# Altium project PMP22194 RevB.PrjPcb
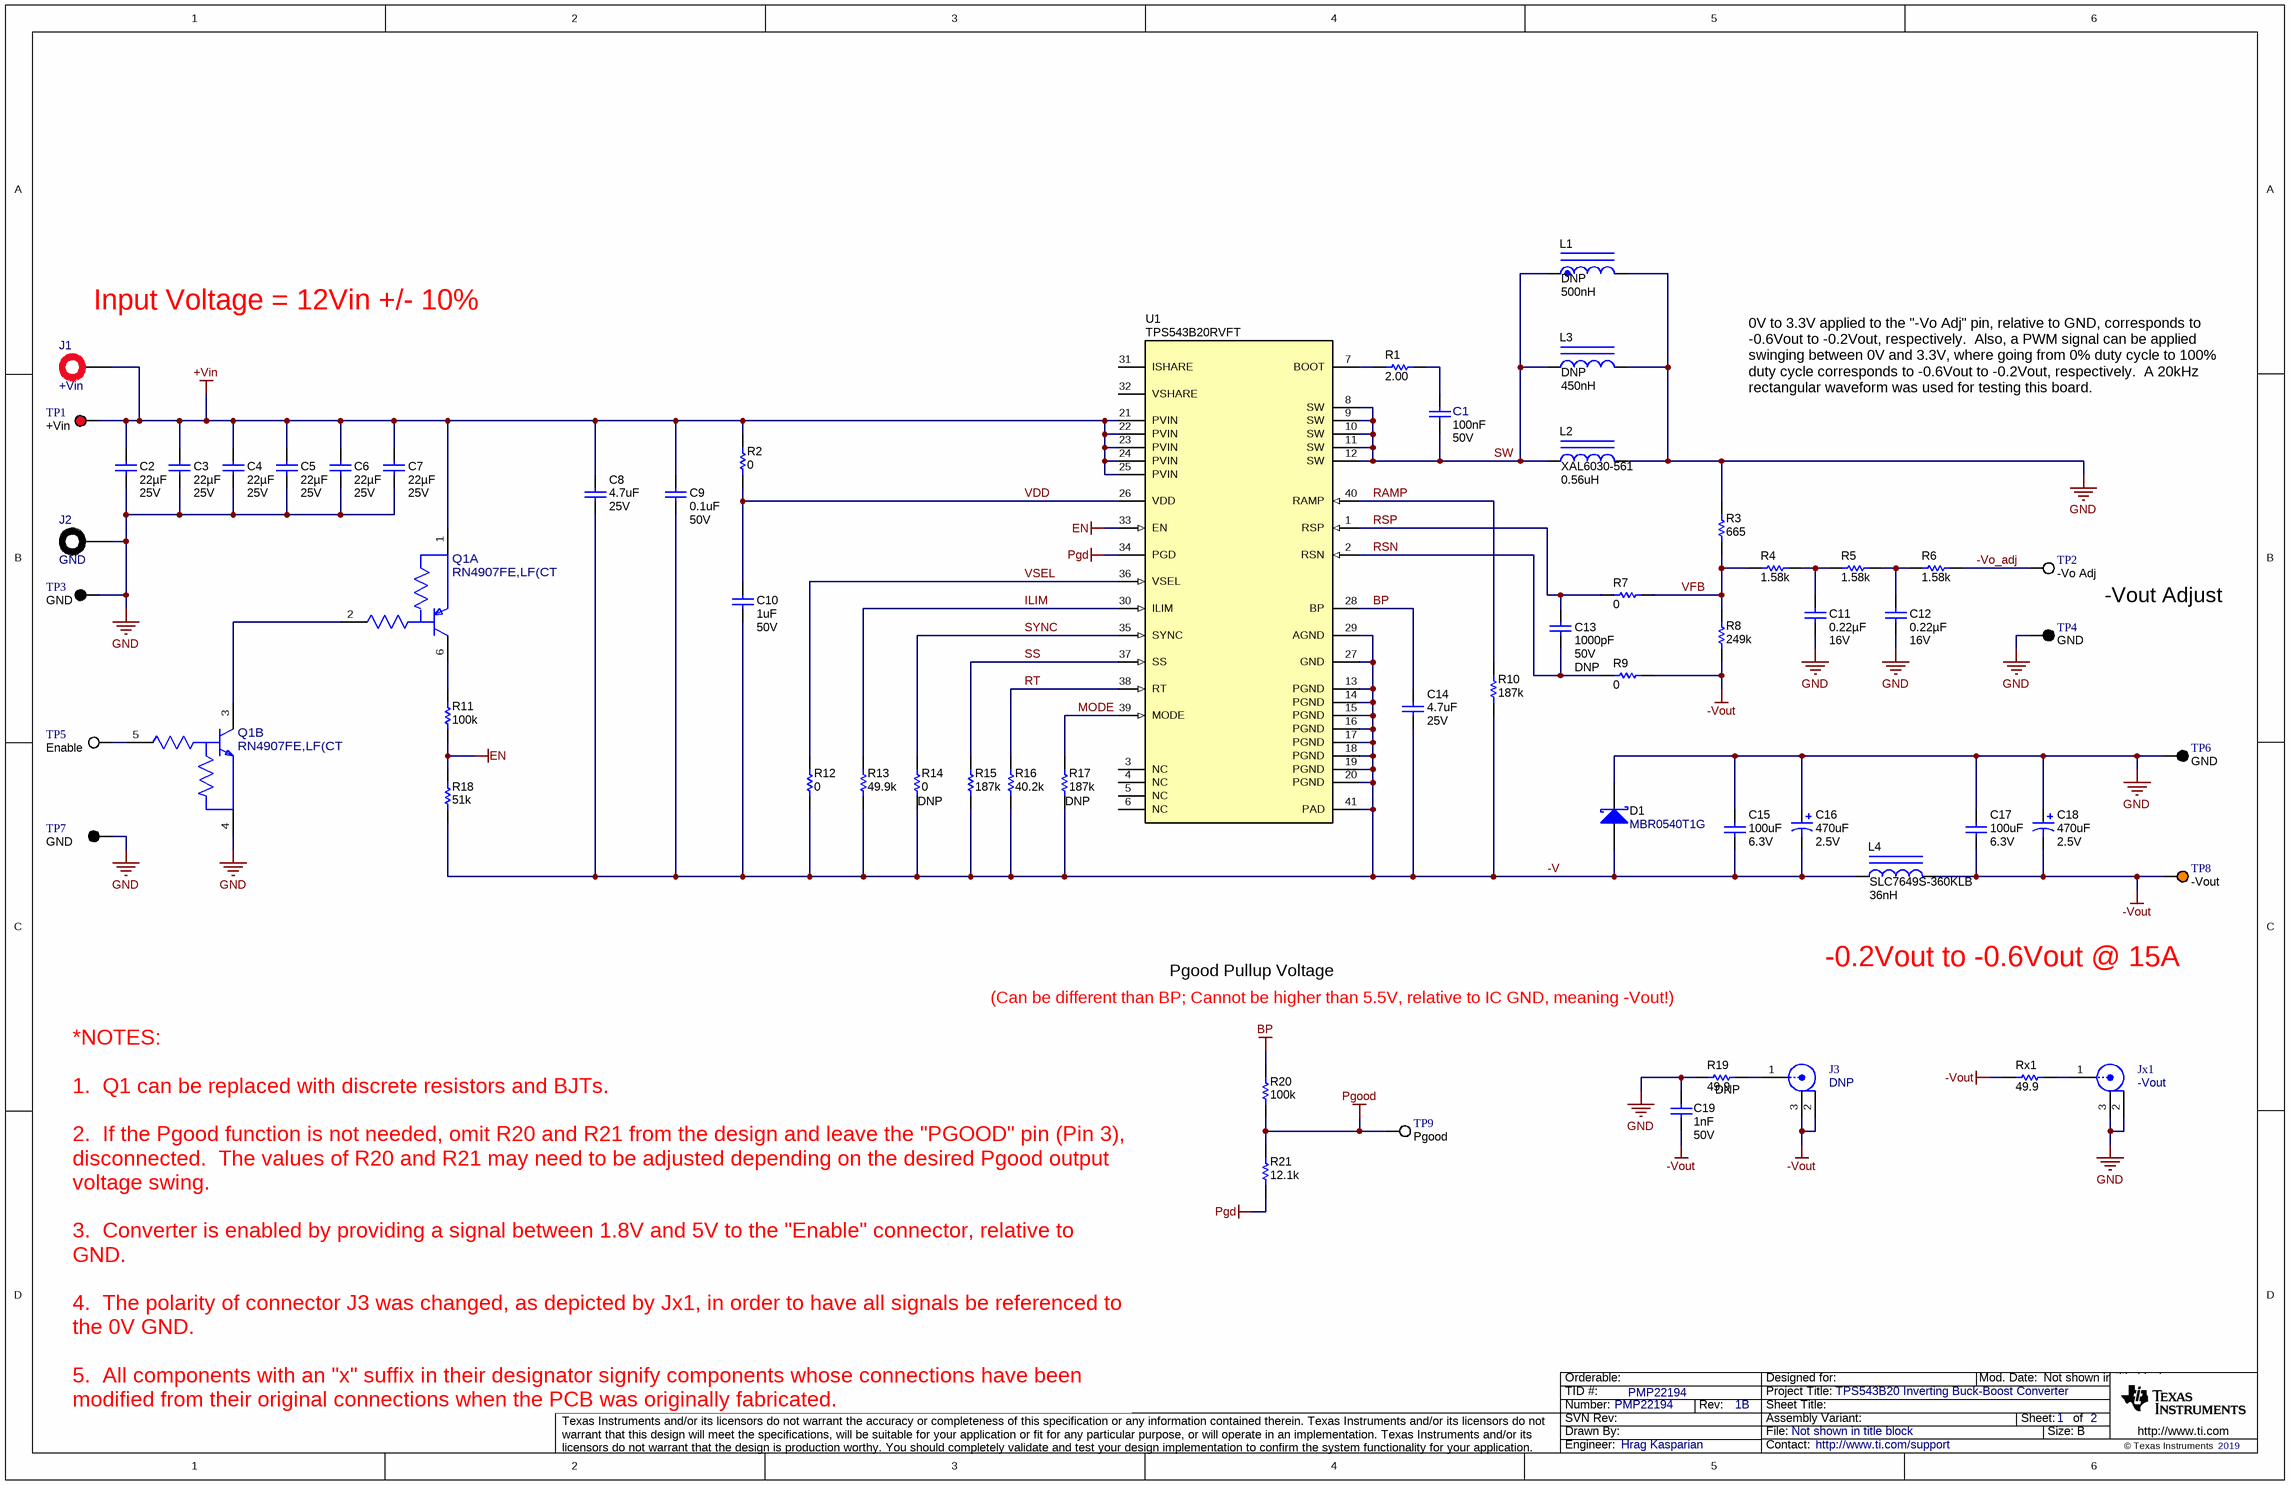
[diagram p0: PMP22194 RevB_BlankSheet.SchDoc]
CopyrightYear: 2019; PCB_Layout: Hrag Kasparian; PCB_Rev: B; PRJ_Engineer: Hrag Kasparian; PRJ_Number: PMP22194; PRJ_Title: TPS543B20 Inverting Buck-Boost Converter; SCH_Rev: 1B; TechSupport: http://www.ti.com/support; TID: PMP22194
2 sheets, 73 parts. Net scope: global (net labels, ports and power ports of the same name join across sheets).
Board file: PMP22194 RevB_PCB.PcbDoc
Sheets:
  PMP22194 RevB_BlankSheet.SchDoc
  PMP22194 RevB_Hardware.SchDoc

## Sheet PMP22194 RevB_BlankSheet.SchDoc
size 431 x 279 mm; Date: Not shown in title block; ApprovedBy: Not shown in title block; CheckedBy: Not shown in title block; Author: Not shown in title block; CompanyName: Not shown in title block; Engineer: Not shown in title block; Organization: Not shown in title block; Address1: Not shown in title block; Address2: Not shown in title block; Address3: Not shown in title block; Address4: Not shown in title block; DocumentNumber: 1; Revision: Use project parameter SCH_Rev; SheetNumber: 1; SheetTotal: 2; PageSetup: Record=PageOptions¦CenterHorizontal=True¦CenterVertical=True¦PrintScale=1.00¦XCorrection=1.00¦YCorrection=1.00¦PrintKind=0¦BorderSize=5000000¦LeftOffset=0¦BottomOffset=0¦Orientation=2¦PaperLength=1000¦PaperWidth=1000¦Scale=100¦PaperSource=15¦PrintQuality=600¦MediaType=1¦DitherType=10¦PaperKind=Letter¦PrintScaleMode=1

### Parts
C1  Cap_F: 100nF  VDC_V: 50V  [FP-CL10B104KB8NNNC_0603-IPC_B]  (hidden comment: CL10B104KB8NNNC)
C2  VDC_V: 25V  ValueDisplayed: 22µF  [1210_270L]  (hidden comment: CL32B226KAJNFNE)
C3  VDC_V: 25V  ValueDisplayed: 22µF  [1210_270L]  (hidden comment: CL32B226KAJNFNE)
C4  VDC_V: 25V  ValueDisplayed: 22µF  [1210_270L]  (hidden comment: CL32B226KAJNFNE)
C5  VDC_V: 25V  ValueDisplayed: 22µF  [1210_270L]  (hidden comment: CL32B226KAJNFNE)
C6  VDC_V: 25V  ValueDisplayed: 22µF  [1210_270L]  (hidden comment: CL32B226KAJNFNE)
C7  VDC_V: 25V  ValueDisplayed: 22µF  [1210_270L]  (hidden comment: CL32B226KAJNFNE)
C8  value 4.7uF  Value1: 25V  [C1206]  (hidden comment: CL31B475KAHNFNE)
C9  VDC_V: 50V  ValueDisplayed: 0.1uF  [0402L]  (hidden comment: GCM155R71H104KE02D)
C10  value 1uF  Value1: 50V  [0805]  (hidden comment: CL21B105KBFNNNG)
C11  VDC_V: 16V  ValueDisplayed: 0.22µF  [0402L]  (hidden comment: CL05B224KO5NNNC)
C12  VDC_V: 16V  ValueDisplayed: 0.22µF  [0402L]  (hidden comment: CL05B224KO5NNNC)
C13  DNP  VDC_V: 50V  ValueDisplayed: 1000pF  [0402L]
C14  value 4.7uF  Value1: 25V  [C1206]  (hidden comment: CL31B475KAHNFNE)
C15  value 100uF  Value1: 6.3V  [C1206]  (hidden comment: GRM31CR60J107KE39L)
C16  value 470uF  Value1: 2.5V  [7343-20]  (hidden comment: 2R5TPE470M9)
C17  value 100uF  Value1: 6.3V  [C1206]  (hidden comment: GRM31CR60J107KE39L)
C18  value 470uF  Value1: 2.5V  [7343-20]  (hidden comment: 2R5TPE470M9)
C19  Cap_F: 1nF  VDC_V: 50V  [0603L]  (hidden comment: CL10B102KB8NNNC)
D1  MBR0540T1G  [SOD-123]
J1  +Vin  [Cinch_108-0902-001]
J2  GND  [Cinch_108-0903-001]
J3  DNP  [CONN_UFL-R-SMT-1]
Jx1  -Vout  [CONN_UFL-R-SMT-1]
L1  DNP  ValueDisplayed: 500nH  [XAR7030]
L2  value 0.56uH  (hidden comment: XAL6030-561)
L3  DNP  ValueDisplayed: 450nH  [MLC1240]
L4  SLC7649S-360KLB  ValueDisplayed: 36nH  [SLC7649]
Q1  RN4907FE,LF(CT  [FP-RN4907FE,LF(CT_SOT-6-MFG]  (parts A,B of 2)
R1  ValueDisplayed: 2.00  [0603L]  (hidden comment: CRCW06032R00FKEA)
R2  ValueDisplayed: 0  [0603L]  (hidden comment: RC0603JR-070RL)
R3  ValueDisplayed: 665  [0402L]  (hidden comment: CRCW0402665RFKED)
R4  ValueDisplayed: 1.58k  [0402L]  (hidden comment: CRCW04021K58FKED)
R5  ValueDisplayed: 1.58k  [0402L]  (hidden comment: CRCW04021K58FKED)
R6  ValueDisplayed: 1.58k  [0402L]  (hidden comment: CRCW04021K58FKED)
R7  ValueDisplayed: 0  [0402L]  (hidden comment: RC0402JR-070RL)
R8  ValueDisplayed: 249k  [0402L]  (hidden comment: CRCW0402249KFKED)
R9  ValueDisplayed: 0  [0402L]  (hidden comment: RC0402JR-070RL)
R10  ValueDisplayed: 187k  [0402]  (hidden comment: CRCW0402187KFKED)
R11  ValueDisplayed: 100k  [0402L]  (hidden comment: CRCW0402100KJNED)
R12  ValueDisplayed: 0  [0402L]  (hidden comment: RC0402JR-070RL)
R13  ValueDisplayed: 49.9k  [0402]  (hidden comment: CRCW040249K9FKED)
R14  DNP  ValueDisplayed: 0  [0402L]
R15  ValueDisplayed: 187k  [0402]  (hidden comment: CRCW0402187KFKED)
R16  ValueDisplayed: 40.2k  [0402]  (hidden comment: CRCW040240K2FKED)
R17  DNP  ValueDisplayed: 187k  [0402]
R18  ValueDisplayed: 51k  [0402L]  (hidden comment: CRCW040251K0JNED)
R19  DNP  ValueDisplayed: 49.9  [0402L]
R20  ValueDisplayed: 100k  [0402L]  (hidden comment: CRCW0402100KFKED)
R21  ValueDisplayed: 12.1k  [0402L]  (hidden comment: CRCW040212K1FKED)
Rx1  ValueDisplayed: 49.9  [0402L]  (hidden comment: RC0402FR-0749R9L)
TP1  +Vin  [Keystone5010]
TP2  -Vo Adj  [Keystone5012]
TP3  GND  [Keystone5011]
TP4  GND  [Keystone5011]
TP5  Enable  [Keystone5012]
TP6  GND  [Keystone5011]
TP7  GND  [Keystone5011]
TP8  -Vout  [Keystone5013]
TP9  Pgood  [Keystone5012]
U1  TPS543B20RVFT  [RVF0040A_SMD_NV]

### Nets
+Vin: C2.1 C3.1 C4.1 C5.1 C6.1 C7.1 C8.1 C9.1 J1.1 Q1.1(1_E) R2.2 TP1.1 U1.21(PVIN) U1.22(PVIN) U1.23(PVIN) U1.24(PVIN) U1.25(PVIN)
-Vout: C17.2 C18.2(-) C19.2 J3.2 J3.3 L4.2 R8.1 R9.1 Rx1.1 TP8.1
BP: C14.1 R20.2 U1.28(BP)
EN: R11.1 R18.2 U1.33(EN)
GND: C2.2 C3.2 C4.2 C5.2 C6.2 C7.2 C11.2 C12.2 C15.1 C16.1(+) C17.1 C18.1(+) C19.1 D1.1(K) J2.1 Jx1.2 Jx1.3 L1.2 L2.2 L3.2 Q1.4(2_E) R3.2 R19.1 TP3.1 TP4.1 TP6.1 TP7.1
Pgd: R21.1 U1.34(PGD)
Pgood: R20.1 R21.2 TP9.1
-V: C8.2 C9.2 C10.2 C14.2 C15.2 C16.2(-) D1.2(A) L4.1 R10.1 R12.1 R13.1 R14.1 R15.2 R16.1 R17.1 R18.1 U1.13(PGND) U1.14(PGND) U1.15(PGND) U1.16(PGND) U1.17(PGND) U1.18(PGND) U1.19(PGND) U1.20(PGND) U1.27(GND) U1.29(AGND) U1.41(PAD)
-Vo_adj: R6.2 TP2.1
ILIM: R13.2 U1.30(ILIM)
MODE: R17.2 U1.39(MODE)
RAMP: R10.2 U1.40(RAMP)
RSN: C13.2 R9.2 U1.2(RSN)
RSP: C13.1 R7.2 U1.1(RSP)
RT: R16.2 U1.38(RT)
SS: R15.1 U1.37(SS)
SW: C1.1 L1.1 L2.1 L3.1 U1.8(SW) U1.9(SW) U1.10(SW) U1.11(SW) U1.12(SW)
SYNC: R14.2 U1.35(SYNC)
VDD: C10.1 R2.1 U1.26(VDD)
VFB: R3.1 R4.1 R7.1 R8.2
VSEL: R12.2 U1.36(VSEL)
NetC1_2: C1.2 R1.2
NetC11_1: C11.1 R4.2 R5.1
NetC12_1: C12.1 R5.2 R6.1
NetJ3_1: J3.1 R19.2
NetJx1_1: Jx1.1 Rx1.2
NetQ1_2: Q1.2(1_B) Q1.3(2_C)
NetQ1_5: Q1.5(2_B) TP5.1
NetQ1_6: Q1.6(1_C) R11.2
NetR1_1: R1.1 U1.7(BOOT)

Not connected (* = marked no-connect by the designer): U1 3(NC) 4(NC) 5(NC) 6(NC) 31(ISHARE) 32(VSHARE)

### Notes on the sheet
- (near J1) Input Voltage = 12Vin +/- 10%
- 0V to 3.3V applied to the "-Vo Adj" pin, relative to GND, corresponds to -0.6Vout to -0.2Vout, respectively.  Also, a PWM signal can be applied swinging between 0V and 3.3V, where going from 0% duty cycle to 100% duty cycle corresponds to -0.6Vout to -0.2Vout, respectively.  A 20kHz rectangular waveform was used for testing this board.
- -Vout Adjust
- Pgood Pullup Voltage
- -0.2Vout to -0.6Vout @ 15A
- (Can be different than BP; Cannot be higher than 5.5V, relative to IC GND, meaning -Vout!)
- *NOTES:
  1.  Q1 can be replaced with discrete resistors and BJTs.
  2.  If the Pgood function is not needed, omit R20 and R21 from the design and leave the "PGOOD" pin (Pin 3), disconnected.  The values of R20 and R21 may need to be adjusted depending on the desired Pgood output voltage swing.
  3.  Converter is enabled by providing a signal between 1.8V and 5V to the "Enable" connector, relative to GND.
  4.  The polarity of connector J3 was changed, as depicted by Jx1, in order to have all signals be referenced to the 0V GND.
  5.  All components with an "x" suffix in their designator signify components whose connections have been modified from their original connections when the PCB was originally fabricated.

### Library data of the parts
C1 = CMP-0087079-2: CAP CER 0.1UF 50V X7R 0603; Manufacturer: Samsung; SizeZ_mm: 0.9mm; AEC Qualified: No; TempCo: 15%; Symbol Name: SYM-CL10B104KB8NNNC; Tolerance_%: 10%
C2-C7 = CMP-0080066-1: CAP, CERM, 22 µF, 25 V,+/- 10%, X7R, 1210; Manufacturer: Samsung Electro-Mechanics; TaMin_C: -55°C; Polarized: N; SizeAreaWB_mm2: 14.7; U/M: EA; Value: 22uF; TaMax_C: 125°C; SizeZ_mm: 2.7; SizeX_mm: 3.2; SizeY_mm: 2.5; Cap_Case: 1210; SizeArea_mm2: 8; AEC Category: Q200
C8 C14 = Capacitor: CAP, CERM, 4.7uF, 25V, X7R, 10%, 1206; Manufacturer: Samsung; Polarized: N; U/M: EA
C9 = CMP-0006356-2: CAP, CERM, 0.1 uF, 50 V, +/- 10%, X7R, AEC-Q200 Grade 1, 0402; Manufacturer: MuRata; TaMin_C: -55°C; Polarized: N; SizeAreaWB_mm2: 3; Value1: Unknown; U/M: EA; Value: 0.1uF; TaMax_C: 125°C; SizeZ_mm: 0.6; SizeX_mm: 1; SizeY_mm: 0.5; Cap_Case: 0402; AEC Qualified: Y; Cap_F: 100nF; AEC Category: Q200
C10 = Capacitor: CAP, CERM, 1uF, 50V, X7R, 10%, 0805; Manufacturer: Samsung; Polarized: N; U/M: EA
C11 C12 = CMP-0860563-1: CAP, CERM, 0.22 µF, 16 V,+/- 10%, X7R, 0402; Manufacturer: Samsung Electro-Mechanics; SizeX_mm: 1; Cap_Case: 0402; Green_REACh: Incomplete; TaMin_C: -55°C; SizeArea_mm2: 0.5; TaMax_C: 125°C; U/M: EA; Green_Lifecycle: Active; SizeAreaWB_mm2: 3; AEC Qualified: N; SizeZ_mm: 0.6; AEC Category: Q200; Cap_F: 220nF; Value: 0.22uF
C13 = CMP-0006412-2: CAP, CERM, 1000 pF, 50 V, +/- 5%, C0G/NP0, 0402; Manufacturer: MuRata; PartNumber: GRM1555C1H102JA01D; TaMin_C: -55°C; Polarized: N; SizeAreaWB_mm2: 3; Value1: Unknown; U/M: EA; Value: 1000pF; TaMax_C: 125°C; SizeZ_mm: 0.6; SizeX_mm: 1; SizeY_mm: 0.5; Cap_Case: 0402; Cap_F: 1nF; AEC Category: Q200
C15 C17 = Capacitor: CAP, CERM, 100uF, 6.3V, X5R, 10%, 1206; Manufacturer: Murata; Polarized: N; U/M: EA
C16 C18 = Capacitor_Polarized: CAP, Molded Tantalum Polymer, 470uF, 2.5V, +/-20%, 9mOhm ESR, SMT; Manufacturer: Panasonic; Polarized: Y; U/M: EA
C19 = CMP-0084856-1: CAP, CERM, 1000 pF, 50 V,+/- 10%, X7R, 0603; Manufacturer: Samsung Electro-Mechanics; SizeArea_mm2: 1.28; ValueDisplayed: 1000pF; Cap_Case: 0603; SizeZ_mm: 1; TaMin_C: -55°C; Value: 1000pF; SizeY_mm: 0.8; SizeX_mm: 1.6; Polarized: N; SizeAreaWB_mm2: 4.68; AEC Category: Q200; U/M: EA; TaMax_C: 125°C
D1 = CMP-0028526-2: Diode, Schottky, 40 V, 0.5 A, SOD-123; Manufacturer: ON Semiconductor; Green_REACh: Passed; SizeY_mm: 1.7; Io_A: 500mA; SizeArea_mm2: 6.545; RJC_CperW: 118; Green_Lifecycle: Active; Vr_V: 40V; Vf_V: 510mV; TJmax_C: 150°C; AEC Category: Q101; SizeAreaWB_mm2: 13.095; Value1: 0.5A; SizeZ_mm: 1.35; SizeX_mm: 3.85; Value2: 0.51V; Value: 40V
J1 = CMP-0079575-1: Banana Jack Insul Nylon Red, TH; PartNumber: 108-0902-001; Manufacturer: Cinch Connectivity; Gender: Female; Current_A: 15A; Green_REACh: Incomplete; ContactFinish: Tin; Green_Lifecycle: Active
J2 = CMP-0079574-1: Banana Jack Insul Nylon Black, TH; PartNumber: 108-0903-001; Manufacturer: Cinch Connectivity; Gender: Female; Current_A: 15A; Green_REACh: Incomplete; ContactFinish: Tin; Green_Lifecycle: Active
J3 Jx1 = CMP-0075320-1: Receptacle, Ultra Miniature Coaxial, Male Pin, 50 ohm, SMT; Manufacturer: Hirose Electric Co. Ltd.; PartNumber: U.FL-R-SMT-1(01); CNHeader: False; Gender: Female; ContactFinish: Gold
L1 = CMP-0084759-1: Inductor, Shielded, Composite, 500 nH, 17.5 A, 0.0033 ohm, SMD; PartNumber: XAR7030-501MEB; Manufacturer: Coilcraft; AEC Category: Q200; DCR_ohm: 3.3m; Irms: 17.5A @ 40C rise; Value2: 17.5A; SizeX_mm: 8.5; SizeArea_mm2: 72.25; Value: 500nH; SizeZ_mm: 5; AEC Qualified: N; Isat: 36A @ 30% inductance drop; SizeAreaWB_mm2: 110.25
L2 = Inductor_Iron: Inductor, Wirewound, Composite, 0.56uH, 29A Isat, 3.4 mOhm, SMT; Manufacturer: Coilcraft; U/M: EA
L3 = CMP-0060545-1: Inductor, Square Pot Core, Powdered Iron, 450 nH, 19.8 A, 0.00173 ohm, SMD; Manufacturer: Coilcraft; PartNumber: MLC1240-451MLB; Isat: 24.9A @ 20% inductance drop; Irms: 19.8A @ 40C rise; Green_Lifecycle: Not Set; SizeAreaWB_mm2: 165; DCR_ohm: 1.73m; Green_REACh: Incomplete; Value: 450nH; Imax_A: 19.8A; SizeZ_mm: 4.1; SizeX_mm: 10.5; SizeY_mm: 11.2; SizeArea_mm2: 117.6; AEC Category: Q200
L4 = CMP-0060903-1: Inductor, Shielded, Ferrite, 36 nH, 39 A, 0.00017 ohm, SMD; Manufacturer: Coilcraft; Isat: 100A @ 20% inductance drop; Irms: 39A @ 40C rise; Green_Lifecycle: Not Set; SizeAreaWB_mm2: 91.2938; DCR_ohm: 170µ; Green_REACh: Incomplete; Value: 36nH; Imax_A: 39A; SizeZ_mm: 4.96; SizeX_mm: 7.62; SizeY_mm: 7.49; SizeArea_mm2: 57.0738; AEC Category: Q200
Q1 = CMP-0086797-1: Bipolar Transistors - Pre-Biased Bias Resistor Built-in transistor; Manufacturer: Toshiba; PNP: 1; SizeZ_mm: 0.6mm; AEC Qualified: No; Value: -50/50V
R1 = CMP-0022302-4: RES, 2.00, 1%, 0.1 W, AEC-Q200 Grade 0, 0603; Manufacturer: Vishay-Dale; Power_W: 100mW; TempCo: 100 ppm/C; Value_Code: 2R00; Value: 2.00; EIA_Code: E96; Res_ohm: 2; SizeX_mm: 1.6; SizeY_mm: 0.8; SizeZ_mm: 1; Value2: 0.1W; SizeArea_mm2: 1.28; AEC Qualified: Y; VDC_V: 75V; AEC Category: Q200; AEC Grade: 0
R2 = CMP-0025885-5: RES, 0, 5%, 0.1 W, 0603; Manufacturer: Yageo; Power_W: 100mW; TempCo: 200 ppm/C; Value_Code: 0000; Value: 0; EIA_Code: E24; SizeX_mm: 1.6; SizeZ_mm: 1; Value2: 0.1W; SizeArea_mm2: 1.28; AEC Qualified: N; VDC_V: 75V; AEC Category: Q200; SizeY_mm: 0.8; SizeAreaWB_mm2: 4.68
R3 = CMP-0026501-2: RES, 665, 1%, 0.063 W, AEC-Q200 Grade 0, 0402; Manufacturer: Vishay-Dale; Power_W: 63mW; TempCo: 100 ppm/C; Value_Code: 665R; Value: 665; EIA_Code: E96; SizeX_mm: 1; SizeY_mm: 0.5; SizeZ_mm: 0.6; Value2: 0.063W; AEC Qualified: Y; VDC_V: 50V; AEC Category: Q200; AEC Grade: 0
R4-R6 = CMP-0026090-3: RES, 1.58 k, 1%, 0.063 W, AEC-Q200 Grade 0, 0402; Manufacturer: Vishay-Dale; Power_W: 63mW; TempCo: 100 ppm/C; Value_Code: 1k58; Value: 1.58k; EIA_Code: E96; SizeX_mm: 1; SizeY_mm: 0.5; SizeZ_mm: 0.6; Value2: 0.063W; AEC Qualified: Y; VDC_V: 50V; AEC Category: Q200; AEC Grade: 0
R7 R9 R12 = CMP-0027004-2: RES, 0, 5%, 0.063 W, 0402; Manufacturer: Yageo America; Power_W: 63mW; TempCo: 200 ppm/C; Value_Code: 0000; U/M: EA; Value: 0; EIA_Code: E24; SizeX_mm: 1; SizeY_mm: 0.5; SizeZ_mm: 0.6; Value2: 0.063W; VDC_V: 50V; AEC Category: Q200
R8 = CMP-0026193-2: RES, 249 k, 1%, 0.063 W, AEC-Q200 Grade 0, 0402; Manufacturer: Vishay-Dale; Power_W: 63mW; TempCo: 100 ppm/C; Value: 249k; EIA_Code: E96; SizeX_mm: 1; SizeY_mm: 0.5; SizeZ_mm: 0.6; Value2: 0.063W; AEC Qualified: Y; VDC_V: 50V; AEC Category: Q200; AEC Grade: 0
R10 R15 = CMP-0026056-3: RES, 187 k, 1%, 0.063 W, AEC-Q200 Grade 0, 0402; Manufacturer: Vishay-Dale; Power_W: 63mW; TempCo: 100 ppm/C; Value: 187k; EIA_Code: E96; SizeX_mm: 1; SizeY_mm: 0.5; SizeZ_mm: 0.6; Value2: 0.063W; AEC Qualified: Y; VDC_V: 50V; AEC Category: Q200; AEC Grade: 0
R11 = CMP-0026823-3: RES, 100 k, 5%, 0.063 W, AEC-Q200 Grade 0, 0402; Manufacturer: Vishay-Dale; Power_W: 63mW; TempCo: 200 ppm/C; Value: 100k; EIA_Code: E24; SizeX_mm: 1; SizeY_mm: 0.5; SizeZ_mm: 0.6; Value2: 0.063W; AEC Qualified: Y; VDC_V: 50V; AEC Category: Q200; AEC Grade: 0
R13 = CMP-0026403-2: RES, 49.9 k, 1%, 0.063 W, AEC-Q200 Grade 0, 0402; Manufacturer: Vishay-Dale; Power_W: 63mW; TempCo: 100 ppm/C; Value_Code: 49k9; Value: 49.9k; EIA_Code: E96; SizeX_mm: 1; SizeY_mm: 0.5; SizeZ_mm: 0.6; Value2: 0.063W; AEC Qualified: Y; VDC_V: 50V; AEC Category: Q200; AEC Grade: 0
R14 = CMP-0027004-2: RES, 0, 5%, 0.063 W, 0402; Manufacturer: Yageo America; PartNumber: RC0402JR-070RL; Power_W: 63mW; TempCo: 200 ppm/C; Value_Code: 0000; U/M: EA; Value: 0; EIA_Code: E24; SizeX_mm: 1; SizeY_mm: 0.5; SizeZ_mm: 0.6; Value2: 0.063W; VDC_V: 50V; AEC Category: Q200
R16 = CMP-0026367-2: RES, 40.2 k, 1%, 0.063 W, AEC-Q200 Grade 0, 0402; Manufacturer: Vishay-Dale; Power_W: 63mW; TempCo: 100 ppm/C; Value_Code: 40k2; Value: 40.2k; EIA_Code: E96; SizeX_mm: 1; SizeY_mm: 0.5; SizeZ_mm: 0.6; Value2: 0.063W; AEC Qualified: Y; VDC_V: 50V; AEC Category: Q200; AEC Grade: 0
R17 = CMP-0026056-3: RES, 187 k, 1%, 0.063 W, AEC-Q200 Grade 0, 0402; Manufacturer: Vishay-Dale; PartNumber: CRCW0402187KFKED; Power_W: 63mW; TempCo: 100 ppm/C; Value: 187k; EIA_Code: E96; SizeX_mm: 1; SizeY_mm: 0.5; SizeZ_mm: 0.6; Value2: 0.063W; AEC Qualified: Y; VDC_V: 50V; AEC Category: Q200; AEC Grade: 0
R18 = CMP-0026945-3: RES, 51 k, 5%, 0.063 W, AEC-Q200 Grade 0, 0402; Manufacturer: Vishay-Dale; Power_W: 63mW; TempCo: 200 ppm/C; Value_Code: 51k0; Value: 51k; EIA_Code: E24; SizeX_mm: 1; SizeY_mm: 0.5; SizeZ_mm: 0.6; Value2: 0.063W; AEC Qualified: Y; VDC_V: 50V; AEC Category: Q200; AEC Grade: 0
R19 = CMP-0026738-1: RES, 49.9, 1%, 0.063 W, 0402; Manufacturer: Yageo America; PartNumber: RC0402FR-0749R9L; Power_W: 63mW; TempCo: 100 ppm/C; Value_Code: 49R9; U/M: EA; Value: 49.9; EIA_Code: E96; SizeX_mm: 1; SizeY_mm: 0.5; SizeZ_mm: 0.6; Value2: 0.063W; AEC Qualified: N; VDC_V: 50V; AEC Category: Q200
R20 = CMP-0025950-3: RES, 100 k, 1%, 0.063 W, AEC-Q200 Grade 0, 0402; Manufacturer: Vishay-Dale; Power_W: 63mW; TempCo: 100 ppm/C; Value: 100k; EIA_Code: E96; SizeX_mm: 1; SizeY_mm: 0.5; SizeZ_mm: 0.6; Value2: 0.063W; AEC Qualified: Y; VDC_V: 50V; AEC Category: Q200; AEC Grade: 0
R21 = CMP-0025991-3: RES, 12.1 k, 1%, 0.063 W, AEC-Q200 Grade 0, 0402; Manufacturer: Vishay-Dale; Power_W: 63mW; TempCo: 100 ppm/C; Value_Code: 12k1; Value: 12.1k; EIA_Code: E96; SizeX_mm: 1; SizeY_mm: 0.5; SizeZ_mm: 0.6; Value2: 0.063W; AEC Qualified: Y; VDC_V: 50V; AEC Category: Q200; AEC Grade: 0
Rx1 = CMP-0026738-1: RES, 49.9, 1%, 0.063 W, 0402; Manufacturer: Yageo America; Power_W: 63mW; TempCo: 100 ppm/C; Value_Code: 49R9; U/M: EA; Value: 49.9; EIA_Code: E96; SizeX_mm: 1; SizeY_mm: 0.5; SizeZ_mm: 0.6; Value2: 0.063W; AEC Qualified: N; VDC_V: 50V; AEC Category: Q200
TP1 = CMP-0055147-1: Test Point, Multipurpose, Red, TH; Manufacturer: Keystone; CNHeader: FALSE; Green_Lifecycle: Active; Green_REACh: Passed; ContactFinish: Silver; CT: TRUE
TP2 TP5 TP9 = CMP-0055149-1: Test Point, Multipurpose, White, TH; Manufacturer: Keystone; CNHeader: FALSE; Green_Lifecycle: Active; Green_REACh: Passed; ContactFinish: Silver; CT: TRUE
TP3 TP4 TP6 TP7 = CMP-0055148-1: Test Point, Multipurpose, Black, TH; Manufacturer: Keystone; CNHeader: FALSE; Green_Lifecycle: Active; Green_REACh: Passed; ContactFinish: Silver; CT: TRUE
TP8 = CMP-0055150-1: Test Point, Multipurpose, Orange, TH; Manufacturer: Keystone; CNHeader: FALSE; Green_Lifecycle: Active; Green_REACh: Passed; ContactFinish: Silver; CT: TRUE
U1 = CMP-0014068-8: 4-19Vin 25A Stackable Synchronous Step-down SWIFT(TM) Converter w/ Adaptive Internal Compensation, RVF0040A (LQFN-CLIP-40); Alternate PartNumber: TPS543B20RVFR; Manufacturer: Texas Instruments; SizeZ_mm: 1.52; SizeX_mm: 5; SizeY_mm: 7; SizeArea_mm2: 35; CompType: IC; SizeAreaWB_mm2: 63; AEC Category: Q200; AEC Qualified: N; Rating: Catalog

## Sheet PMP22194 RevB_Hardware.SchDoc
size 431 x 279 mm; Date: Not shown in title block; ApprovedBy: Not shown in title block; CheckedBy: Not shown in title block; Author: Not shown in title block; CompanyName: Not shown in title block; Engineer: Not shown in title block; Organization: Not shown in title block; Address1: Not shown in title block; Address2: Not shown in title block; Address3: Not shown in title block; Address4: Not shown in title block; DocumentNumber: 2; Revision: Use project parameter SCH_Rev; SheetNumber: 2; SheetTotal: 2; PageSetup: Record=PageOptions¦CenterHorizontal=True¦CenterVertical=True¦PrintScale=1.00¦XCorrection=1.00¦YCorrection=1.00¦PrintKind=0¦BorderSize=5000000¦LeftOffset=0¦BottomOffset=0¦Orientation=2¦PaperLength=1000¦PaperWidth=1000¦Scale=100¦PaperSource=15¦PrintQuality=600¦MediaType=1¦DitherType=10¦PaperKind=Letter¦PrintScaleMode=1
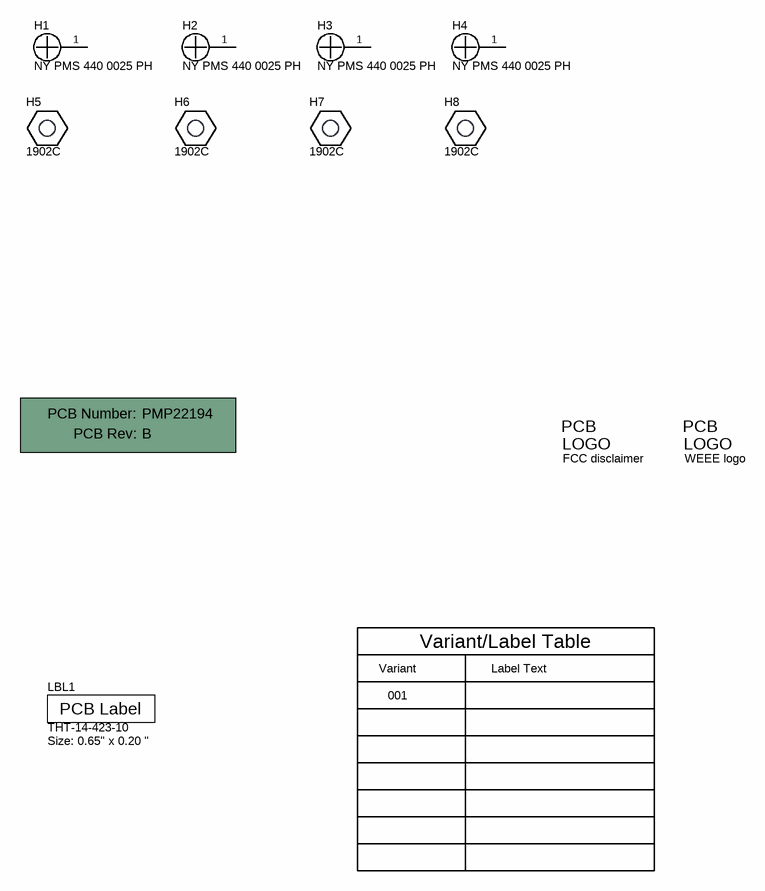
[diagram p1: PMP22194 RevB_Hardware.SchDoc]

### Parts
!PCB1  Printed Circuit Board  (value not drawn)  (mechanical)
H1  NY PMS 440 0025 PH  [NY PMS 440 0025 PH]
H2  NY PMS 440 0025 PH  [NY PMS 440 0025 PH]
H3  NY PMS 440 0025 PH  [NY PMS 440 0025 PH]
H4  NY PMS 440 0025 PH  [NY PMS 440 0025 PH]
H5  1902C  [Keystone_1902C]
H6  1902C  [Keystone_1902C]
H7  1902C  [Keystone_1902C]
H8  1902C  [Keystone_1902C]
LBL1  THT-14-423-10  Note: Size: 0.65" x 0.20 "  [Label_650x200]
Logo1  FCC disclaimer  [FCC_disclaimer]  (no BOM)
Logo2  WEEE logo  [WEEE_Minimum]  (no BOM)

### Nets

Not connected (* = marked no-connect by the designer): H1 1; H2 1; H3 1; H4 1

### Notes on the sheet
- Variant
- Variant/Label Table
- Label Text
- 001

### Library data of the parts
!PCB1 = CMP-0003618-2: Manufacturer: Any; PartNumber: PMP22194
H1-H4 = CMP-0003617-1: Machine Screw, Round, #4-40 x 1/4, Nylon, Philips panhead; Manufacturer: B&F Fastener Supply; CompType: Hardware
H5-H8 = CMP-0003610-1: Standoff, Hex, 0.5"L #4-40 Nylon; Manufacturer: Keystone; CompType: Hardware
LBL1 = CMP-0003625-1: Thermal Transfer Printable Labels, 0.650" W x 0.200" H - 10,000 per roll; Manufacturer: Brady; CompType: Label
Logo1 = CMP-0074847-1: FCC_disclaimer; Library Reference: Logo
Logo2 = CMP-0074769-1

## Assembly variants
001: not fitted C13 J3 L1 L3 R14 R17 R19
